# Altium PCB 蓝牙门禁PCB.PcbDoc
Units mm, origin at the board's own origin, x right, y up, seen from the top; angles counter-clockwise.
Board outline 99.95 x 68.33 mm, 2 copper layers (Top Layer, Bottom Layer); 17 components, 26 nets, 120 pads, 27 vias.
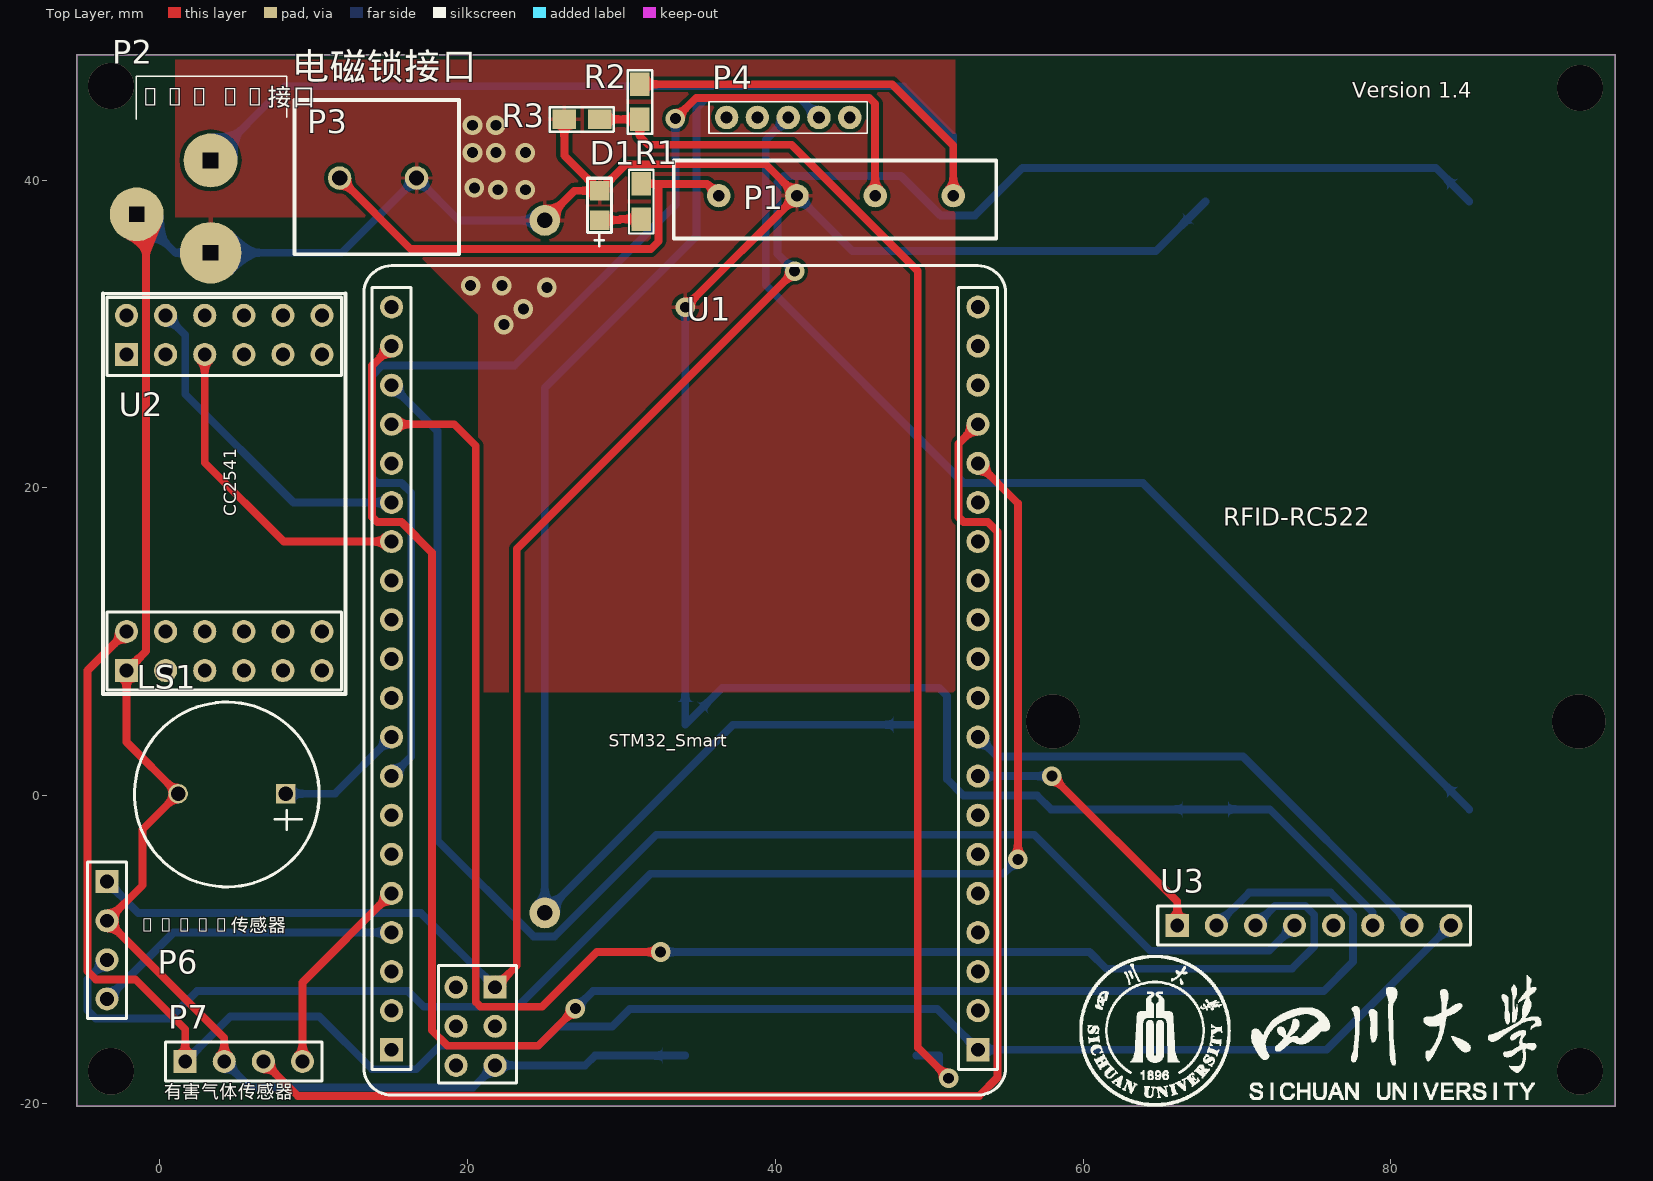
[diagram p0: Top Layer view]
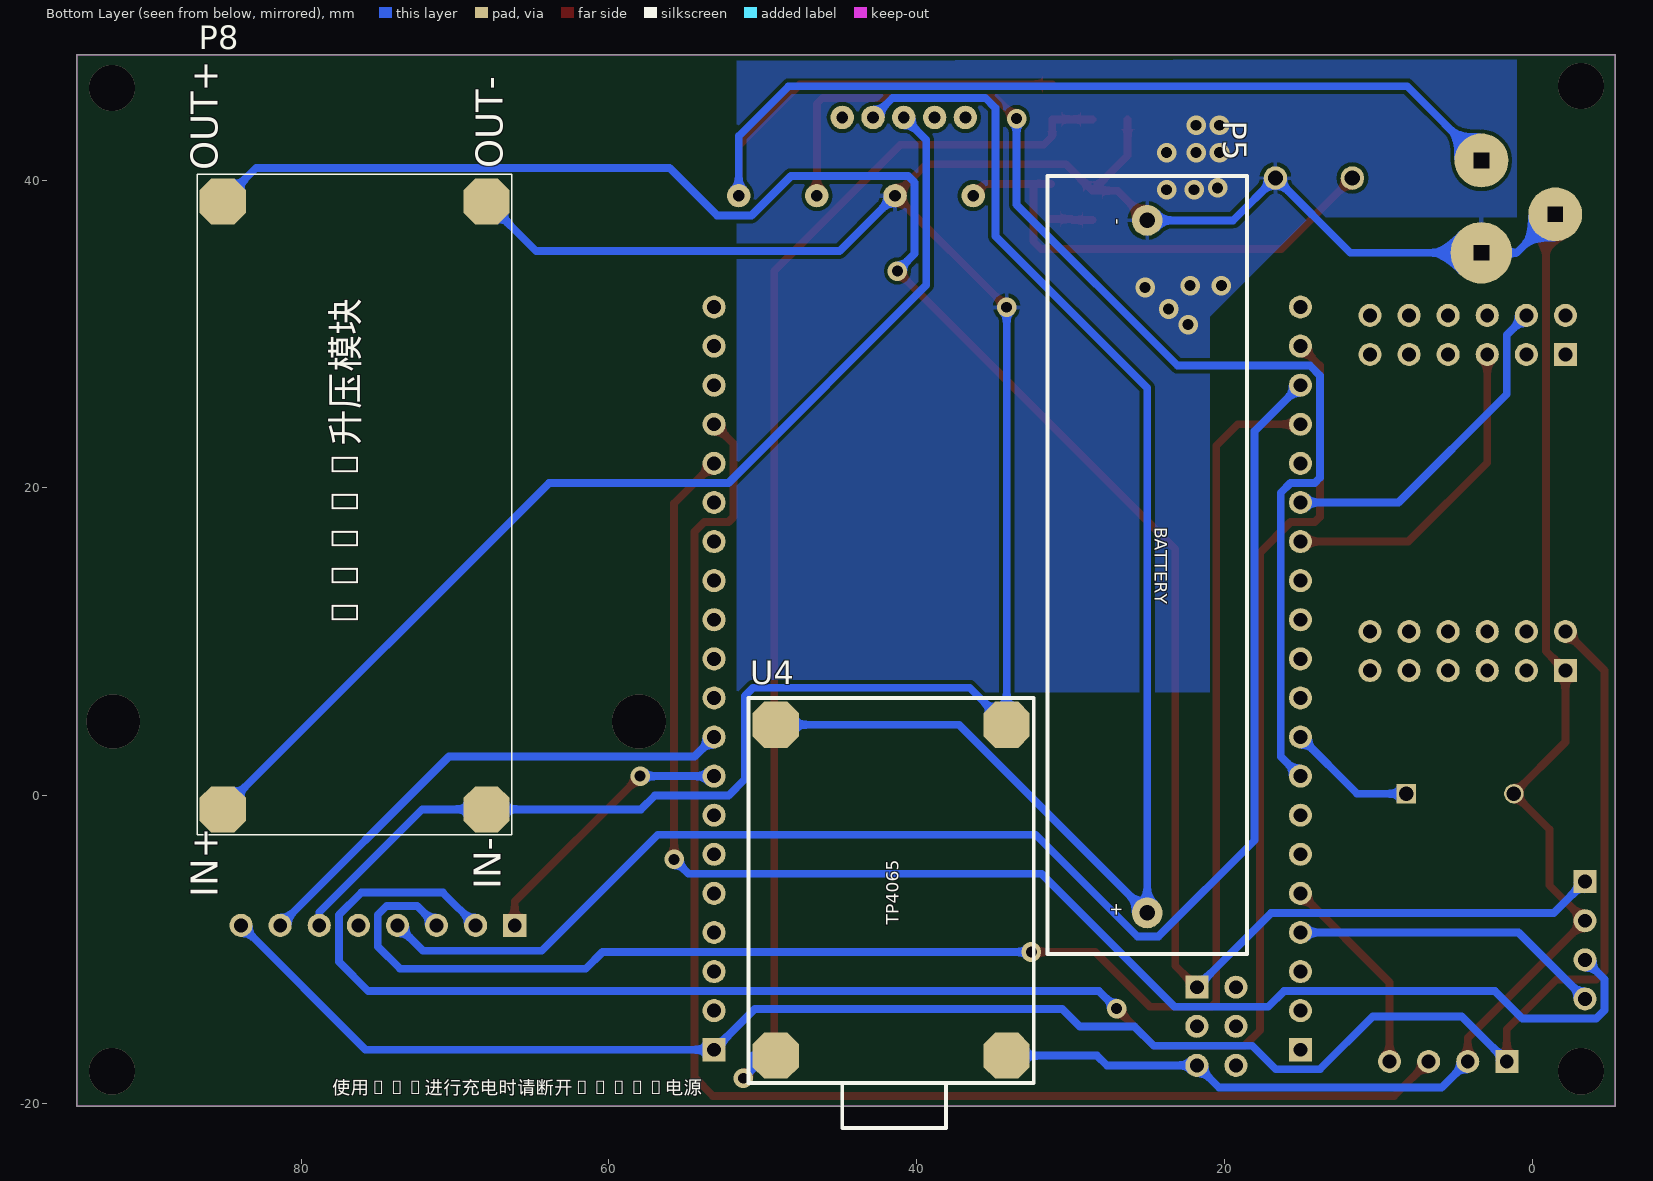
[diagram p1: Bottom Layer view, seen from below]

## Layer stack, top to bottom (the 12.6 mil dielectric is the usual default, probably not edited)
Top Solder: solder mask 0.0102, Solder Resist, Dk 3.5
Top Layer: signal copper 0.0356
Dielectric 1: dielectric 0.32, FR-4, Dk 4.8
Bottom Layer: signal copper 0.0356
Bottom Solder: solder mask 0.0102, Solder Resist, Dk 3.5

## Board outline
-5.386,48.133 94.563,48.133 94.563,-20.193 -5.386,-20.193

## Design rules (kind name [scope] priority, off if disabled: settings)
Clearance [All] p1: gap=0.254
PolygonConnect [All] p1: connectstyle=Relief reliefconductorwidth=0.254 reliefentries=4 polygonreliefangle="90 Angle" airgapwidth=0.254
RoutingVias [All] p1: holewidth=0.711 width=1.27 viastyle="Through Hole" minholewidth=0.711 minwidth=1.27 maxholewidth=0.711 maxwidth=1.27
SolderMaskExpansion [All] p1: expansion=0.102
Width [All] p1: maxlimit=1.27 minlimit=0.254 preferedwidth=0.508 minimp=50.000000 maximp=50.000000 favimp=50.000000
30 further rules are at their usual default settings.

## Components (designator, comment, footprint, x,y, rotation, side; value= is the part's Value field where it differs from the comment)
D1 "LED0" 0805-led 28.575,38.354 r90 top
LS1 "Bell" BUZZER-12MM 4.445,0.127 r180 top
P1 "干簧继电器" 干簧继电器SIP-1A05 51.562,38.989 r180 top
P2 "12V电源" DC-005(5.5MM) 3.302,41.275 r270 top
P3 "接电磁锁" 接线端子-0.5 11.684,40.132 r0 top
P4 "电源开关" 拨动开关（2mm） 44.831,44.069 r180 top
P5 "电池座" 7号电池盒-4.5CM 25.019,-6.731 r90 bottom
P6 "MQ-2接口" HDR1X4 -3.429,-5.588 r270 top
P7 "雾霾传感器接口" HDR1X4 1.651,-17.272 r0 top
P8 "升压模块" DC-DC升压模块 85.09,-0.889 r90 bottom
R1 "500" 0805-SMALL 31.271,39.752 r270 top
R2 "100欧" 0805-SMALL 31.19,46.228 r270 top
R3 "100欧" 0805-SMALL 28.575,43.942 r180 top
U1 "STM32" STM32_Smart 15.061,-16.51 r270 top
U2 "CC2541" Smart_RF_2541 -2.159,8.128 r90 top
U3 "RC522" HDR1X8 66.114,-8.428 r0 top
U4 "TP4065" TP4065_模块 49.149,-16.891 r90 bottom

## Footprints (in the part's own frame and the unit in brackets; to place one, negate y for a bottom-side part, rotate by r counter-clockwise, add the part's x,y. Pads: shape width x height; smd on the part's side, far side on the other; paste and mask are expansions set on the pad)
7号电池盒-4.5CM [mm]
  round 2 hole 1: 1(-0.889,0) 2(44.111,0)
  silkscreen extent -3.56,-6.48 46.99,6.48
0805-led [mil]
  rect 50x50 smd: 1(-37.5,0) 2(37.5,0)
  silkscreen extent -105,-31 69,31
0805-SMALL [mil]
  rect 60x50 smd: 1(0,0) 2(90,0)
  silkscreen extent -36,-31 127,32
BUZZER-12MM [mm]
  rect 1.27x1.27 hole 0.95: 1(-3.75,0)
  round 1.27 hole 0.95: 2(3.25,0)
  silkscreen extent -5.91,-5.95 6.09,6.05
DC-005(5.5MM) [mm]
  round 3.5 hole 1 square: 1(0,0) 2(3.5,-4.8)
  round 4 hole 1 square: 3(6,0)
  silkscreen extent -5.46,-4.83 -2.67,4.95
DC-DC升压模块 [mil]
  oct 118.11x118.11 / inner oct 118.11x118.11 / far side oct 0x0 all layers, no hole: 1(0,0) 2(0,-675) 3(1555,0) 4(1555,-675)
  silkscreen extent -65,-740 1625,65
HDR1X4 [mm] "Connector; Header; 4 Position"
  rect 1.5x1.5 hole 0.9: 1(0,0)
  round 1.5 hole 0.9: 2(2.54,0) 3(5.08,0) 4(7.62,0)
  silkscreen extent -1.27,-1.27 8.89,1.27
HDR1X8 [mm] "Connector; Header; 8 Position"
  rect 1.5x1.5 hole 0.9: 1(0,0)
  round 1.5 hole 0.9: 2(2.54,0) 3(5.08,0) 4(7.62,0) 5(10.16,0) 6(12.7,0) 7(15.24,0) 8(17.78,0)
  silkscreen extent -1.27,-1.27 19.05,1.27
Smart_RF_2541 [mm]
  rect 1.5x1.5 hole 0.9: 1(0,0) 13(20.54,0)
  round 1.5 hole 0.9: 2(0,-2.54) 3(0,-5.08) 4(0,-7.62) 5(0,-10.16) 6(0,-12.7) 7(2.54,-12.7) 8(2.54,-10.16) 9(2.54,-7.62) 10(2.54,-5.08) 11(2.54,-2.54) 12(2.54,0) 14(20.54,-2.54) 15(20.54,-5.08) 16(20.54,-7.62) 17(20.54,-10.16) 18(20.54,-12.7) 19(23.08,-12.7) 20(23.08,-10.16) 21(23.08,-7.62) 22(23.08,-5.08) 23(23.08,-2.54) 24(23.08,0)
  silkscreen extent -1.52,-14.22 24.51,1.52
STM32_Smart [mm]
  rect 1.5x1.5 hole 0.9: 1(0,38.1) 40(0,0) 46(-4.064,6.731)
  round 1.5 hole 0.9: 2(-2.54,38.1) 3(-5.08,38.1) 4(-7.62,38.1) 5(-10.16,38.1) 6(-12.7,38.1) 7(-15.24,38.1) 8(-17.78,38.1) 9(-20.32,38.1) 10(-22.86,38.1) 11(-25.4,38.1) 12(-27.94,38.1) 13(-30.48,38.1) 14(-33.02,38.1) 15(-35.56,38.1) 16(-38.1,38.1) 17(-40.64,38.1) 18(-43.18,38.1) 19(-45.72,38.1) 20(-48.26,38.1) 21(-48.26,0) 22(-45.72,0) 23(-43.18,0) 24(-40.64,0) 25(-38.1,0) 26(-35.56,0) 27(-33.02,0) 28(-30.48,0) 29(-27.94,0) 30(-25.4,0) 31(-22.86,0) 32(-20.32,0) 33(-17.78,0) 34(-15.24,0) 35(-12.7,0) 36(-10.16,0) 37(-7.62,0) 38(-5.08,0) 39(-2.54,0) 41(-4.064,4.191) 42(-1.524,4.191) 43(1.016,4.191) 44(1.016,6.731) 45(-1.524,6.731)
  silkscreen extent -50.95,-1.8 2.94,39.9
TP4065_模块 [mm]
  oct 3x3 / inner oct 3x3 / far side oct 0x0 all layers, no hole: 1(0,0) 2(0,-15) 3(21.5,-15) 4(21.5,0)
  silkscreen extent -4.7,-16.76 23.24,1.78
干簧继电器SIP-1A05 [mil]
  round 60 hole 30: 1(0,0) 2(200,0) 3(400,0) 4(600,0)
  silkscreen extent -110,-90 715,110
拨动开关（2mm） [mil]
  round 60 hole 30: 0(0,0) 0(314.96,0) 1(78.74,0) 2(157.48,0) 3(236.22,0)
  silkscreen extent -45,-40 360,40
接线端子-0.5 [mil]
  round 60 hole 39.37: 1(0,0) 2(196.85,0)
  silkscreen extent -115,-195 305,200

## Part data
D1: "Typical INFRARED GaAs LED"
LS1: "Electrical Bell"
P1 P6 P7 P8: library part "Header 4", "Header, 4-Pin"
P2 P4: library part "Header 3", "Header, 3-Pin"
P3: library part "Header 2H", "Header, 2-Pin, Right Angle"
P5: library part "Header 2", "Header, 2-Pin"
R1 R2 R3: library part RES2
U1: library part STM32_Smart
U2: library part Smart_RF_2541
U3: library part RFID_RC522
U4: library part "TP4056_ 模块"

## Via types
v1: diameter 1.27, hole 0.711, Top Layer to Bottom Layer, 21 vias
v2: diameter 3, hole 3, Top Layer to Bottom Layer, 4 vias
v3: diameter 3.5, hole 3.5, Top Layer to Bottom Layer, 2 vias

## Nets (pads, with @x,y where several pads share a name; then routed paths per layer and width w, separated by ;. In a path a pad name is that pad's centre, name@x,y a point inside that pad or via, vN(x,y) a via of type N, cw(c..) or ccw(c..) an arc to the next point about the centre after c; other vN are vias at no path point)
ADC1: P6.3 U1.16 | length 96.4
  Top Layer w0.508: U1.16 55.757,18.994 v1(55.757,-4.139)
  Bottom Layer w0.508: P6.3 -4.695,-11.934 -4.695,-13.944 -4.162,-14.477 0.639,-14.477 2.417,-12.699 16.133,-12.699 17.149,-13.715 23.245,-13.715 31.881,-5.079 54.817,-5.079 v1(55.757,-4.139)
ADC2: P7.3 U1.17 | length 94.1
  Top Layer w0.508: P7.3 8.965,-19.506 53.242,-19.506 54.436,-18.312 54.436,17.146 53.801,17.781 52.226,17.781 51.903,18.104 51.903,22.872 U1.17
GND: D1.2 LS1.2 P1.3 P2.2 P2.3 P3.2 P5.2 P6.2 P7.2 P8.2 P8.4 R3.2 U1.44 U2.1 U3.6 U4.2 U4.3 | length 271.7
  Top Layer w0.508: P2.2 -0.885,37.775 -0.885,9.402 U2.1 -2.159,3.481 LS1.2 -1.114,-2.182 -1.114,-5.813 P6.2 4.191,-15.748 P7.2 ; P5.2 26.946,39.306 D1.2 ; R3.2 26.289,41.592 D1.2 ; v1(34.149,31.736) P1.3 39.369,41.022 30.291,41.022 D1.2
  Bottom Layer w0.508: P2.2 1.002,35.275 P2.3 11.827,35.275 P3.2 19.436,37.38 P5.2 ; P7.2 5.892,-18.973 20.345,-18.973 U1.44 27.639,-17.526 28.274,-16.891 U4.2 ; v1(34.149,31.736) U4.3 36.551,7.011 50.626,7.011 51.159,6.478 51.159,1.068 52.226,0.001 57.016,0.001 57.906,-0.889 P8.2 72.119,-0.889 78.814,-7.584 U3.6 ; P1.3 45.008,35.383 64.72,35.383 P8.4
  other v1: 22.352,30.607 23.622,31.623 25.146,33.02 20.193,33.147 22.225,33.147 21.971,39.37 23.749,39.37 20.447,39.497 20.32,41.783 21.844,41.783 23.749,41.783 20.32,43.561 21.844,43.561
IRQ: U3.5
MISO: U1.23 U3.4 | length 95.6
  Bottom Layer w0.508: U1.23 18.038,23.693 18.038,-2.895 24.286,-9.143 25.658,-9.143 32.262,-2.539 56.823,-2.539 64.367,-10.083 72.079,-10.083 U3.4
MOSI: U1.24 U3.3 | length 106
  Top Layer w0.508: U1.24 19.131,24.13 20.527,22.734 20.527,-13.399 20.843,-13.715 24.839,-13.715 28.395,-10.159 v1(32.541,-10.159)
  Bottom Layer w0.508: v1(32.541,-10.159) 60.405,-10.159 61.497,-11.251 73.562,-11.251 75.01,-9.803 75.01,-7.746 74.426,-7.162 72.46,-7.162 U3.3
NetD1_1: D1.1 R1.2 | length 2.7
  Top Layer w0.508: D1.1 29.874,37.401 29.938,37.466 R1.2
NetP1_4: P1.4 P3.1 R1.1 | length 32.1
  Top Layer w0.508: P3.1 16.306,35.51 31.906,35.51 32.414,36.018 32.414,39.498 32.16,39.752 ; R1.1 32.16,39.752 ; P1.4 35.559,39.752 32.16,39.752
NetR2_2: R2.2 R3.1 U4.1 | length 81.9
  Top Layer w0.508: R3.1 R2.2 31.19,42.846 31.744,42.292 41.05,42.292 49.254,34.088 49.254,-16.357 v1(51.261,-18.363)
  Bottom Layer w0.508: U4.1 50.651,-16.891 50.651,-17.754 v1(51.261,-18.363)
P21: U2.11
P22: U2.2
PB4: LS1.1 U1.32 | length 8.4
  Bottom Layer w0.508: LS1.1 11.378,0.127 U1.32
PB5: P1.2 U1.33 | length 78.1
  Top Layer w0.508: v1(33.506,43.994) 34.852,45.34 46.105,45.34 46.482,44.963 P1.2
  Bottom Layer w0.508: U1.33 16.336,2.545 16.336,19.686 15.701,20.321 14.126,20.321 13.796,20.651 13.796,27.306 14.431,27.941 23.041,27.941 33.506,38.406 v1(33.506,43.994)
PB8: P7.4 U1.36 | length 13.3
  Top Layer w0.508: P7.4 9.271,-12.14 U1.36
PB9: P6.4 U1.37 | length 20.3
  Bottom Layer w0.508: P6.4 0.889,-8.89 U1.37
RESET: U2.13
RST: U1.9 U3.7 | length 33.3
  Bottom Layer w0.508: U1.9 54.43,2.541 70.385,2.541 U3.7
SCK: U1.22 U3.2 | length 123.4
  Top Layer w0.508: U1.22 13.796,27.945 13.796,18.111 14.126,17.781 15.701,17.781 17.682,15.8 17.682,-15.239 18.698,-16.255 24.591,-16.255 v1(27.004,-13.842)
  Bottom Layer w0.508: v1(27.004,-13.842) 28.147,-12.699 75.627,-12.699 77.532,-10.794 77.532,-7.746 76.084,-6.298 70.784,-6.298 U3.2
SDA: U1.8 U3.1 | length 17.9
  Top Layer w0.508: v1(57.967,1.27) 66.114,-6.877 U3.1
  Bottom Layer w0.508: U1.8 v1(57.967,1.27)
STM32RX-2541TX: U1.27 U2.15 | length 21.3
  Top Layer w0.508: U2.15 2.921,21.642 8.053,16.51 U1.27
STM32TX-2541RX: U1.26 U2.23 | length 22
  Bottom Layer w0.508: U2.23 1.655,29.934 1.655,26.087 8.691,19.05 U1.26
VCC: P1.1 P2.1 R2.1 | length 80.7
  Top Layer w0.508: R2.1 47.579,46.228 51.562,42.245 P1.1
  Bottom Layer w0.508: P2.1 8.128,46.101 48.315,46.101 51.562,42.854 P1.1
VCC3.3: P7.1 U1.1 U2.12 U3.8 | length 124.1
  Top Layer w0.508: U2.12 -4.695,8.132 -4.695,-11.404 -4.162,-11.937 -1.597,-11.937 1.651,-15.185 P7.1
  Bottom Layer w0.508: P7.1 4.573,-14.35 10.367,-14.35 13.796,-17.779 16.666,-17.779 18.19,-16.255 24.591,-16.255 25.848,-14.997 29.403,-14.997 30.533,-13.867 50.518,-13.867 U1.1 75.812,-16.51 U3.8
VCC5: P6.1 P8.3 U1.46 | length 137.3
  Top Layer w0.508: U1.46 23.194,-11.044 23.194,16.028 v1(41.253,34.088)
  Bottom Layer w0.508: P6.1 -1.398,-7.619 16.965,-7.619 U1.46 ; v1(41.253,34.088) 40.132,35.209 40.132,39.849 40.542,40.259 48.162,40.259 50.726,37.695 52.963,37.695 56.061,40.793 82.905,40.793 P8.3
VCCBAT: P4.2 P8.1 | length 71.3
  Bottom Layer w0.508: P4.2 39.37,42.608 39.37,33.177 52.226,20.321 63.88,20.321 P8.1
VCCD: P4.1 P5.1 U4.4 | length 94.3
  Bottom Layer w0.508: P4.1 41.561,45.339 35.538,45.339 34.874,44.675 34.874,36.345 25.019,26.49 P5.1 37.248,4.609 U4.4
pads on no net: P4.0 P4.3 U1.2 U1.3 U1.4 U1.5 U1.6 U1.7 U1.10 U1.11 U1.12 U1.13 U1.14 U1.15 U1.18 U1.19 U1.20 U1.21 U1.25 U1.28 U1.29 U1.30 U1.31 U1.34 U1.35 U1.38 U1.39 U1.40 U1.41 U1.42 U1.43 U1.45 U2.3 U2.4 U2.5 U2.6 U2.7 U2.8 U2.9 U2.10 U2.14 U2.16 U2.17 U2.18 U2.19 U2.20 U2.21 U2.22 U2.24
copper on no net:
  other v2: -3.175,-17.907 92.277,-17.907 92.277,45.974 -3.175,46.101
  other v3: 58.039,4.826 92.202,4.826

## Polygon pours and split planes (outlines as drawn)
GND on Top Layer "Top Overlay-No Net" (solid): 0.889,48.006 1.016,47.879 1.016,37.592 14.351,37.592 20.701,31.242 20.701,6.731 51.562,6.731 51.689,6.858 51.689,47.879
GND on Bottom Layer "Top Overlay-No Net" (solid, pour order 3): 1.016,47.879 1.016,37.592 13.335,37.592 14.478,37.592 20.828,31.242 20.955,31.115 20.955,6.731 51.689,6.731 51.689,47.752

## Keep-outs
Keep-Out Layer:
  lines w0.1: -5.386,-20.193 -5.386,48.133 94.563,48.133 94.563,-20.193 89.864,-20.193 -5.386,-20.193

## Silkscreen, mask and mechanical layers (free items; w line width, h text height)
Top Overlay:
  drawing of 5726 lines, arcs and shapes, not listed
  text "电磁锁接口" at 8.636,45.974 h3
  text "Version 1.4" at 77.47,45.339 h1
  text "12V DC接口" at -1.397,44.45 h2
  text "RFID-RC522" at 69.088,17.145 h2
  text "PM2.5传感器" at -1.397,-9.144 h1.5
  text "有害气体传感器" at 0.254,-19.939 h1.5
Bottom Overlay:
  text "使用USB进行充电时请断开12VDC电源" at 77.978,-19.685 h1.5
